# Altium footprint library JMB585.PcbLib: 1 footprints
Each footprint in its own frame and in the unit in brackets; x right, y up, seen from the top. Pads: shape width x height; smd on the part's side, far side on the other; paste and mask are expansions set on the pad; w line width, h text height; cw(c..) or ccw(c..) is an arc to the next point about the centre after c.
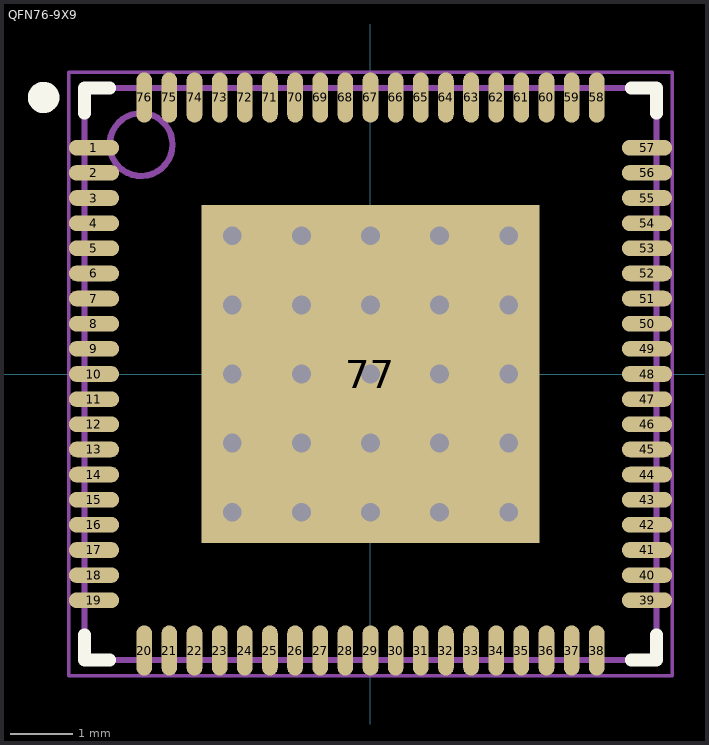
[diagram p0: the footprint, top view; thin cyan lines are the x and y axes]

## QFN76-9X9 [mm]
height 0.9
pads (77):
  oval 0.8x0.25 smd: 1(-4.4,3.6) 2(-4.4,3.2) 3(-4.4,2.8) 4(-4.4,2.4) 5(-4.4,2) 6(-4.4,1.6) 7(-4.4,1.2) 8(-4.4,0.8) 9(-4.4,0.4) 10(-4.4,0) 11(-4.4,-0.4) 12(-4.4,-0.8) 13(-4.4,-1.2) 14(-4.4,-1.6) 15(-4.4,-2) 16(-4.4,-2.4) 17(-4.4,-2.8) 18(-4.4,-3.2) 19(-4.4,-3.6) 39(4.4,-3.6) 40(4.4,-3.2) 41(4.4,-2.8) 42(4.4,-2.4) 43(4.4,-2) 44(4.4,-1.6) 45(4.4,-1.2) 46(4.4,-0.8) 47(4.4,-0.4) 48(4.4,0) 49(4.4,0.4) 50(4.4,0.8) 51(4.4,1.2) 52(4.4,1.6) 53(4.4,2) 54(4.4,2.4) 55(4.4,2.8) 56(4.4,3.2) 57(4.4,3.6)
  oval 0.25x0.8 smd: 20(-3.6,-4.4) 21(-3.2,-4.4) 22(-2.8,-4.4) 23(-2.4,-4.4) 24(-2,-4.4) 25(-1.6,-4.4) 26(-1.2,-4.4) 27(-0.8,-4.4) 28(-0.4,-4.4) 29(0,-4.4) 30(0.4,-4.4) 31(0.8,-4.4) 32(1.2,-4.4) 33(1.6,-4.4) 34(2,-4.4) 35(2.4,-4.4) 36(2.8,-4.4) 37(3.2,-4.4) 38(3.6,-4.4) 58(3.6,4.4) 59(3.2,4.4) 60(2.8,4.4) 61(2.4,4.4) 62(2,4.4) 63(1.6,4.4) 64(1.2,4.4) 65(0.8,4.4) 66(0.4,4.4) 67(0,4.4) 68(-0.4,4.4) 69(-0.8,4.4) 70(-1.2,4.4) 71(-1.6,4.4) 72(-2,4.4) 73(-2.4,4.4) 74(-2.8,4.4) 75(-3.2,4.4) 76(-3.6,4.4)
  rect 5.38x5.38 smd: 77(0,0)
via -2.2,2.2 diameter 0.6 hole 0.3
via -1.1,2.2 diameter 0.6 hole 0.3
via 0,2.2 diameter 0.6 hole 0.3
via 1.1,2.2 diameter 0.6 hole 0.3
via 2.2,2.2 diameter 0.6 hole 0.3
via -2.2,1.1 diameter 0.6 hole 0.3
via -1.1,1.1 diameter 0.6 hole 0.3
via 0,1.1 diameter 0.6 hole 0.3
via 1.1,1.1 diameter 0.6 hole 0.3
via 2.2,1.1 diameter 0.6 hole 0.3
via -2.2,0 diameter 0.6 hole 0.3
via -1.1,0 diameter 0.6 hole 0.3
via 0,0 diameter 0.6 hole 0.3
via 1.1,0 diameter 0.6 hole 0.3
via 2.2,0 diameter 0.6 hole 0.3
via -2.2,-1.1 diameter 0.6 hole 0.3
via -1.1,-1.1 diameter 0.6 hole 0.3
via 0,-1.1 diameter 0.6 hole 0.3
via 1.1,-1.1 diameter 0.6 hole 0.3
via 2.2,-1.1 diameter 0.6 hole 0.3
via -2.2,-2.2 diameter 0.6 hole 0.3
via -1.1,-2.2 diameter 0.6 hole 0.3
via 0,-2.2 diameter 0.6 hole 0.3
via 1.1,-2.2 diameter 0.6 hole 0.3
via 2.2,-2.2 diameter 0.6 hole 0.3
Top Overlay:
  circle w0.25: c-5.2,4.4 r0.125
  lines w0.2: -4.55,-4.15 -4.55,-4.55 -4.15,-4.55 ; -4.55,4.15 -4.55,4.55 -4.15,4.55 ; 4.15,-4.55 4.55,-4.55 4.55,-4.15 ; 4.15,4.55 4.55,4.55 4.55,4.15
Mechanical 13:
  circle w0.1: c-3.65,3.65 r0.5
  lines w0.1: -4.55,-4.55 -4.55,4.55 4.55,4.55 4.55,-4.55 -4.55,-4.55
Mechanical 15:
  lines w0.05: -4.8,-4.8 -4.8,4.8 4.8,4.8 4.8,-4.8 -4.8,-4.8
  lines w0.1: -0.5,0 0.5,0 ; 0,-0.5 0,0.5
3D body "PQFN127P600-8N.step": height 0.9, standoff 0, extent -4.55,-4.55 4.55,4.55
